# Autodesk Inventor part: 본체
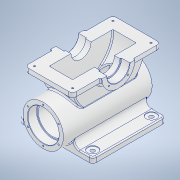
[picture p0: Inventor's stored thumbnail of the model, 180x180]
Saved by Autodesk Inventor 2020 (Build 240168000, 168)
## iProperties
Created: 2023-07
Part Number: 본체
Material: 알루미늄 6061
Document SubType Name: Modeling
Designer: oem
Density: 2.7 g/cm^3
Appearance: 알루미늄 - 평지
Mass: 5726.6 g
Surface Area: 2841.02 cm^2
Volume: 2120.96 cm^3
Author: oem
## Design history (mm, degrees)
sketch "스케치1"
  geometry: C1 r 55 at (0, 0); 1 further point
  constraints: 1 centre point, 1 coincident
  dimensions: "d0" = 110 diameter of C1
extrude "돌출1" new body sketch "스케치1" distance "d1" = 242; taper "d2" = 0 deg
sketch "스케치2"
  geometry: C1 r 55 at (0, 0) reference; C2 r 42.5 at (0, 0)
  constraints: 1 centre point, 1 coincident
  dimensions: "d3" = 85 diameter of C2
extrude "돌출2" cut sketch "스케치2" distance "d4" = 25; taper "d5" = 0 deg
sketch "스케치3" dims "d6" = 97
  geometry: L1 (0, 0)-(0, 48.5); C1 r 55 at (0, 0) reference; 1 further point
  constraints: 2 coincident, 2 end point, 1 vertical, 1 vertical alignment, 2 other
hole "구멍1" sketch "스케치3" at (0, 48.5) diameter "d7" = 4.134; stored, may be unused: countersink angle "d11" = 90 deg, drill point angle "d13" = 118 deg; dims "d8" = 10, "d9" = 4, "d10" = 2, "d12" = 12
sketch "스케치4"
  geometry: C1 r 42.5 at (0, 0) reference; C2 r 38.5 at (0, 0)
  constraints: 1 centre point, 1 coincident
  dimensions: "d17" = 77 diameter of C2
extrude "돌출3" cut sketch "스케치4" extent not by distance; stored distance "d18" = 25; taper "d19" = 0 deg
fillet "모깎기1" dims "d20" = 1.1
node "작업 평면1"
sketch "스케치5"
  geometry: L1 (0, 0)-(0, -60); C1 r 2.067 at (-42.002, 24.25) reference; C2 r 2.067 at (-42.002, -24.25) reference; C3 r 2.067 at (0, -48.5) reference; C4 r 2.067 at (42.002, -24.25) reference; C5 r 2.067 at (42.002, 24.25) reference; C6 r 2.067 at (0, 48.5) reference; C7 r 42.5 at (0, 0) reference; C8 r 55 at (0, 0) reference; C9 r 41.4 at (0, 0) reference
  constraints: 2 end point, 1 vertical
  dimensions: "d22" = 60 distance of L1.start L1.end
node "작업 평면3"
sketch "스케치6"
  geometry: L1 (-42.5, 0)-(42.5, 0) reference; L2 (0, 0)-(100, 0); L3 (0, 0)-(-100, 0); L4 (100, 0)-(100, -35); L5 (100, -35)-(100, -235); L6 (100, -35)-(-100, -35); L7 (-100, -35)-(-100, -235); L8 (-100, -235)-(100, -235); L9 (100, -235)-(100, -35); 2 further points
  constraints: 16 end point, 3 horizontal, 2 parallel, 1 midpoint, 1 perpendicular, 1 vertical
  dimensions: "d24" = 100 distance of L2.start L2.end; "d25" = 100 distance of L2.start L3.end; "d26" = 35 distance of L2.end L4.end; "d29" = 200 distance of L6.end L7.end; "d30" = 200 distance between parallel lines of L5 L7
extrude "돌출4" join sketch "스케치6" distance "d27" = 15; taper "d28" = 0 deg
sketch "스케치8"
  geometry: L1 (100, 35)-(-100, 35) reference; L2 (-100, 35)-(-100, 235) reference; L3 (-100, 235)-(100, 235) reference; L4 (100, 235)-(100, 35) reference; L5 (80, 215)-(-80, 215); L6 (-80, 215)-(-80, 55); L7 (-80, 55)-(80, 55); L8 (80, 55)-(80, 215); L9 (80, 215)-(-80, 55); L10 (-80, 215)-(80, 55); 6 further points
  constraints: 12 end point, 4 coincident, 2 midpoint, 2 parallel, 1 horizontal, 1 perpendicular
  dimensions: "d31" = 160 distance of L7.end L6.end; "d32" = 160 distance of L6.end L5.end; "d33" = 20 distance between parallel lines of L4 L8; "d34" = 20 distance between parallel lines of L1 L7
hole "구멍2" sketch "스케치8" at (-80, 55), (-80, 215), (80, 215), (80, 55) diameter "d35" = 11; stored, may be unused: countersink angle "d39" = 90 deg, drill point angle "d41" = 118 deg; dims "d36" = 10, "d37" = 28, "d38" = 2, "d40" = 15
sketch "스케치9"
  geometry: L1 (0, 15)-(68.377, 15) reference; L2 (0, 0)-(0, 15) reference; L3 (200, 0)-(0, 0) reference; L4 (200, 0)-(200, 15) reference; L5 (131.623, 15)-(200, 15) reference; A1 r 55 centre (100, 60) between (68.377, 15) and (131.623, 15) reference
fillet "모깎기2" dims "d42" = 15
sketch "스케치10"
  geometry: C1 r 2.067 at (-42.002, 24.25) reference; C2 r 2.067 at (-42.002, -24.25) reference; C3 r 2.067 at (0, -48.5) reference; C4 r 2.067 at (42.002, -24.25) reference; C5 r 2.067 at (42.002, 24.25) reference; C6 r 2.067 at (0, 48.5) reference; C7 r 42.5 at (0, 0) reference; C8 r 55 at (0, 0) reference
sketch "스케치11"
  geometry: L1 (-100, -60)-(100, -60) reference; L2 (0, -60)-(0, 100); C1 r 42.5 at (0, 0) reference; C2 r 55 at (0, 0) reference; C3 r 38.5 at (0, 0)
  constraints: 2 end point, 1 centre point, 1 coincident, 1 midpoint, 1 vertical
  dimensions: "d43" = 160 distance of L2.start L2.end
node "작업 평면4"
sketch "스케치12"
  geometry: L1 (0, -242)-(0, -135); L2 (65, -255)-(-65, -255); L3 (-65, -255)-(-65, -15); L4 (-65, -15)-(65, -15); L5 (65, -15)-(65, -255); L6 (65, -255)-(-65, -15); L7 (-65, -255)-(65, -15)
  constraints: 14 end point, 2 midpoint, 2 parallel, 1 horizontal, 1 perpendicular, 1 vertical
  dimensions: "d44" = 107 distance of L1.start L1.end; "d45" = 130 distance of L3.end L4.end; "d46" = 240 distance of L2.end L3.end
extrude "돌출5" join sketch "스케치12" distance "d47" = 15; taper "d48" = 0 deg
node "작업 평면5"
sketch "스케치13"
  geometry: L1 (13, -155)-(13, -45) reference; L2 (13, -45)-(120, -45); L3 (13, -45)-(255, -45) reference; L4 (120, -45)-(120, 0); L5 (0, 0)-(240, 0) reference; L6 (240, -15)-(0, -15) reference; L7 (34.303, -15)-(205.697, -15); A1 r 100 centre (120, 0) between (20, 0) and (220, 0); A2 r 87 centre (120, 0) between (34.303, -15) and (205.697, -15); 3 further points
  constraints: 6 end point, 5 point on line, 4 point on circle, 2 centre point, 2 coincident, 1 midpoint
  dimensions: "d49" = 107 distance of L1.end L2.end; "d50" = 200 diameter of A1; "d51" = 174 diameter of A2
extrude "돌출6" join sketch "스케치13" stored distance "d52" = 90; taper "d53" = 0 deg
sketch "스케치15"
  geometry: L1 (65, 107.5)-(-65, 107.5) reference; L2 (32, 107.5)-(32, 48) reference; L3 (32, 48)-(-32, 48) reference; L4 (-32, 48)-(-32, 107.5) reference; L5 (65, 107.5)-(-65, 107.5) reference; L6 (-65, 255)-(-65, 15) reference; L7 (-65, 15)-(65, 15) reference; L8 (65, 15)-(65, 255) reference; 4 further points
sketch "스케치16"
  geometry: L1 (0, 0)-(240, 0) reference; C1 r 45 at (120, 0); 3 further points
  constraints: 1 centre point, 1 midpoint
  dimensions: "d59" = 90 diameter of C1
extrude "돌출9" join sketch "스케치16" stored distance "d60" = 140; taper "d61" = 0 deg
sketch "스케치17"
  geometry: L1 (165, 0)-(75, 0) reference; C1 r 31 at (120, 0); A1 r 45 centre (120, 0) between (75, 0) and (165, 0) reference; 3 further points
  constraints: 1 centre point, 1 coincident
  dimensions: "d62" = 62 diameter of C1
extrude "돌출10" cut sketch "스케치17" distance "d63" = 23; taper "d64" = 0 deg
fillet "모깎기3" dims "d65" = 1
sketch "스케치18"
  geometry: L1 (90, 0)-(150, 0) reference; C1 r 27.5 at (120, 0); A1 r 30 centre (120, 0) between (90, 0) and (150, 0) reference; 3 further points
  constraints: 1 centre point, 1 coincident
  dimensions: "d66" = 55 diameter of C1
extrude "돌출11" cut sketch "스케치18" extent not by distance; stored distance "d67" = 23; taper "d68" = 0 deg
extrude "돌출12" cut sketch "스케치13" stored distance "d69" = 64; taper "d70" = 0 deg
extrude "돌출13" cut sketch "스케치11" extent not by distance; stored distance "d71" = 0; taper "d72" = 0 deg
sketch "스케치19" dims "d73" = 74
  geometry: L1 (-120, 0)-(-146.163, -26.163); L2 (0, 0)-(-240, 0) reference; L3 (-120, -45)-(-120, 0) reference; L4 (-120, 0)-(-93.837, -26.163); A1 r 45 centre (-120, 0) between (-165, 0) and (-75, 0) reference; 3 further points
  constraints: 4 end point, 3 coincident, 1 symmetric about line, 3 other
  dimensions: "d74" = 45 deg angle of L3 L1
hole "구멍3" sketch "스케치19" at (-93.837, -26.163), (-146.163, -26.163) diameter "d75" = 4.134; stored, may be unused: countersink angle "d79" = 90 deg, drill point angle "d81" = 118 deg; dims "d76" = 10, "d77" = 28, "d78" = 2, "d80" = 12
sketch "스케치20"
  geometry: L1 (49.693, 235)-(-49.693, 235) reference; L2 (65, 180)-(65, 255) reference; L3 (-32, 162.5)-(-32, 222) reference; L4 (-32, 222)-(32, 222) reference; L5 (32, 222)-(32, 162.5) reference; L6 (32, 162.5)-(47, 162.5) reference; L7 (47, 162.5)-(47, 165) reference; L8 (48, 166)-(70, 166) reference; L9 (70, 180)-(70, 166) reference; L10 (70, 180)-(65, 180) reference; L11 (65, 180)-(65, 255) reference; L12 (65, 255)-(-65, 255) reference; L13 (-65, 255)-(-65, 180) reference; L14 (-65, 180)-(-70, 180) reference; L15 (-70, 166)-(-70, 180) reference; L16 (-70, 166)-(-48, 166) reference; L17 (-47, 165)-(-47, 162.5) reference; L18 (-47, 162.5)-(-32, 162.5) reference; L19 (65, 15)-(-65, 15) reference; L20 (0, 15)-(0, 135); L21 (-65, 255)-(65, 255) reference; L22 (52, 242)-(-52, 242); L23 (-52, 242)-(-52, 28); L24 (-52, 28)-(52, 28); L25 (52, 28)-(52, 242); L26 (52, 242)-(-52, 28); L27 (-52, 242)-(52, 28); A1 r 1 centre (48, 165) between (48, 166) and (47, 165) reference; A2 r 1 centre (-48, 165) between (-47, 165) and (-48, 166) reference; 5 further points
  constraints: 14 end point, 4 coincident, 3 midpoint, 2 parallel, 2 perpendicular, 1 horizontal
  dimensions: "d82" = 120 distance of L20.start L20.end; "d83" = 104 distance of L24.end L23.end; "d84" = 214 distance of L23.end L22.end
hole "구멍4" sketch "스케치20" at (-52, 242), (52, 242), (52, 28), (-52, 28) diameter "d85" = 4.917; stored, may be unused: countersink angle "d89" = 90 deg, drill point angle "d91" = 118 deg; dims "d86" = 18, "d87" = 28, "d88" = 2, "d90" = 20
fillet "모깎기4" dims "d92" = 3
fillet "모깎기5" dims "d93" = 10
fillet "모깎기6" dims "d94" = 3
chamfer "모따기1" distance "d95" = 1; stored, may be unused: second distance "d96" = 2, angle "d97" = 45 deg
fillet "모깎기7" dims "d98" = 3
fillet "모깎기8" dims "d99" = 10
node "작업 평면6"
sketch "스케치21"
  geometry: C1 r 42.5 at (0, 0); C2 r 38.5 at (0, 0); 1 further point
  constraints: 2 centre point, 2 coincident
  dimensions: "d101" = 77 diameter of C2
chamfer "모따기2" distance "d102" = 1; stored, may be unused: second distance "d103" = 2, angle "d104" = 45 deg
sketch "스케치22"
  geometry: L1 (43.5, 242)-(-43.5, 242) reference; 1 further point
fillet "모깎기9" dims "d105" = 3
sketch "스케치23"
  geometry: L1 (-69, 104)-(-69, 166) reference; L2 (-69, 135)-(-100, 135); L3 (-100, 45)-(-100, 225) reference; L4 (-100, 135)-(-85, 135); 2 further points
  constraints: 4 end point, 2 midpoint, 1 coincident, 1 point on line, 1 other
  dimensions: "d106" = 15 distance of L2.end L4.end
feature "엠보싱1" sketch "스케치23" dims "d107" = 0.5, "d108" = 0
fillet "모깎기10" dims "d109" = 3
node "솔리드1"
pattern_circular "원형 패턴1" dims angle "d15" = 360 deg
mirror "미러1"
mirror "미러2"
mirror "미러3"
node "투영된 루프2"
node "투영된 루프3"
feature "A9D066F2-1C7D-4E18-AEED-F7BC21143FA4" dims "d35" = 11, "d36" = 10, "d37" = 28, "d38" = 2, "d39" = 90 deg, "d40" = 15, "d41" = 118 deg
other parameters: "d21" = -121, "d100" = -25
